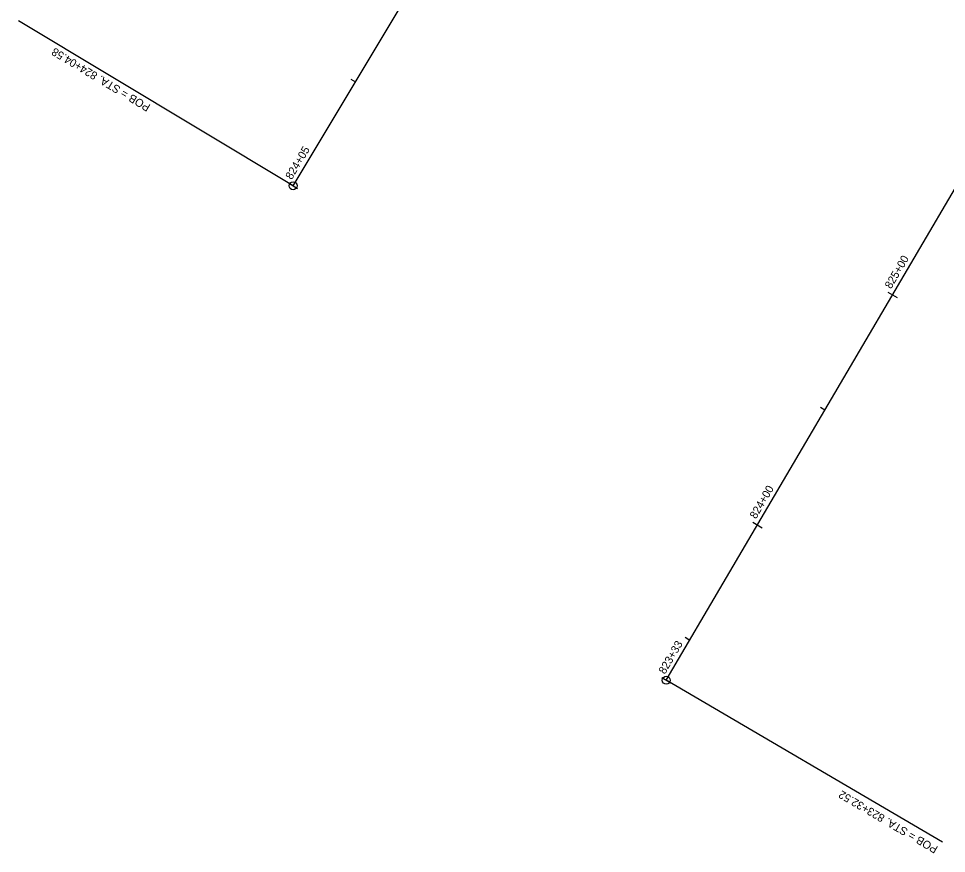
# Model space of a CAD drawing. Extents: x 1160907 to 1161803, y 616778 to 618169.
# Drawn here: x 1160963.4 to 1161311.2, y 616828.7 to 617141.7 of the extents above; entities that cross this region are included whole.
import ezdxf

# ---------------------------------------------------------------- set-up
doc = ezdxf.new("R2010")
doc.units = 0
for name, color, linetype in [('BASE LINE', 7, 'Continuous'), ('D_Roadway_Centerline', 7, 'Continuous'), ('D_Roadway_Centerline_Flags', 7, 'Continuous'), ('D_Roadway_Centerline_Text', 7, 'Continuous')]:
    doc.layers.add(name, color=color, linetype=linetype)

msp = doc.modelspace()

# ---------------------------------------------------------------- linework, layer by layer
at = {"layer": 'BASE LINE'}
for p, q in [((1161066.29, 617079.07), (1161681.91, 618104.18)), ((1161206.19, 616893.68), (1161695.52, 617727.46))]:
    msp.add_line(p, q, dxfattribs=at)
at = {"layer": 'D_Roadway_Centerline'}
for p, q in [((1161066.29, 617079.07), (1161681.91, 618104.18)), ((1161206.19, 616893.68), (1161695.52, 617727.46))]:
    msp.add_line(p, q, dxfattribs=at)
at = {"layer": 'D_Roadway_Centerline_Flags'}
for points in [[(1161066.29, 617079.07), (1160963.41, 617140.85)], [(1161309.68, 616832.94), (1161206.19, 616893.68)]]:
    msp.add_lwpolyline(points, dxfattribs=at)
for centre in [(1161066.29, 617079.07), (1161206.19, 616893.68)]:
    msp.add_circle(centre, 1.5, dxfattribs=at)
at = {"layer": 'D_Roadway_Centerline_Text'}
for points in [[(1161087.96, 617119.03), (1161089.67, 617118)], [(1161064.57, 617080.1), (1161068, 617078.04)], [(1161064.57, 617080.1), (1161068, 617078.04)], [(1161289.24, 617039.14), (1161292.69, 617037.11)], [(1161263.93, 616996.01), (1161265.65, 616995)], [(1161238.62, 616952.89), (1161242.07, 616950.87)], [(1161213.31, 616909.77), (1161215.04, 616908.76)], [(1161204.47, 616894.69), (1161207.92, 616892.67)], [(1161204.47, 616894.69), (1161207.92, 616892.67)]]:
    msp.add_lwpolyline(points, dxfattribs=at)

# ---------------------------------------------------------------- texts
at = {"layer": 'D_Roadway_Centerline_Flags'}
for s, rotation, p in [('POB = STA. 824+04.58', 149.0132, (1161013.09, 617109.26)), ('POB = STA. 823+32.52', 149.5921, (1161308.27, 616831.16))]:
    msp.add_text(s, height=3, rotation=rotation, dxfattribs=at).set_placement(p)
at = {"layer": 'D_Roadway_Centerline_Text'}
for s, rotation, p in [('824+05', 59.0132, (1161065.77, 617081.12)), ('824+05', 59.0132, (1161065.77, 617081.12)), ('825+00', 59.5921, (1161290.43, 617040.18)), ('824+00', 59.5921, (1161239.81, 616953.93)), ('823+33', 59.5921, (1161205.66, 616895.73)), ('823+33', 59.5921, (1161205.66, 616895.73))]:
    msp.add_text(s, height=3, rotation=rotation, dxfattribs=at).set_placement(p)

doc.saveas('drawing.dxf')
